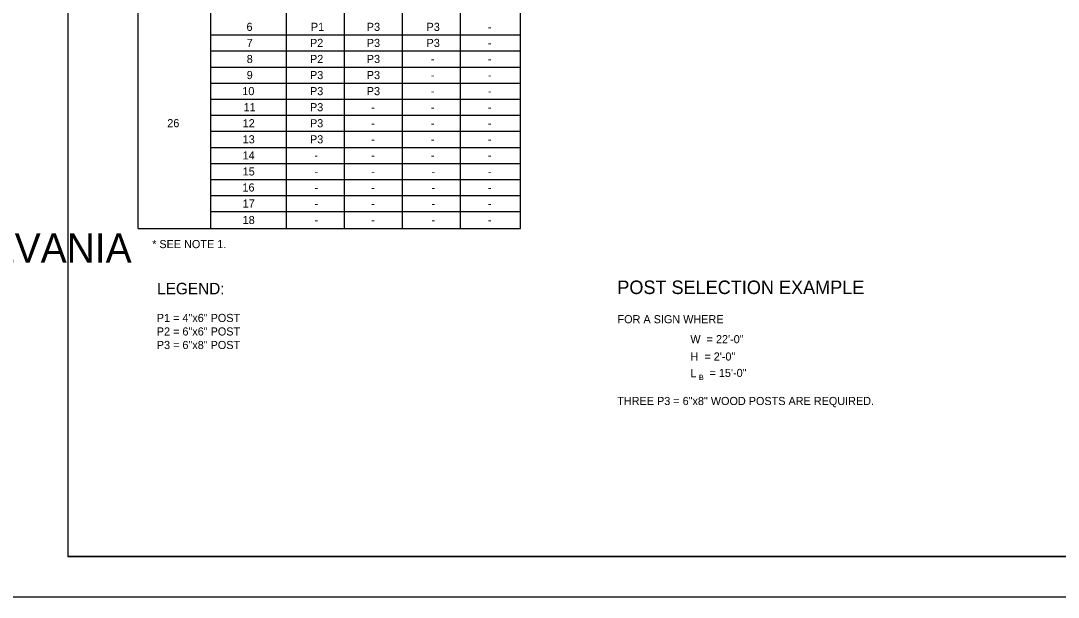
# Model space of a CAD drawing. Extents: x -2340 to 628, y -879 to 309.
# Drawn here: x -253.8 to 130.1, y -284.6 to -71.4 of the extents above; entities that cross this region are included whole.
import ezdxf

# ---------------------------------------------------------------- set-up
doc = ezdxf.new("R2010")
doc.units = 0
for name, color, linetype in [('Level 1', 7, 'Continuous'), ('Level 2', 7, 'Continuous'), ('Level 3', 7, 'Continuous'), ('Level 4', 7, 'Continuous'), ('PLT-BNDY', 7, 'Continuous')]:
    doc.layers.add(name, color=color, linetype=linetype)

msp = doc.modelspace()

# ---------------------------------------------------------------- linework, layer by layer
at = {"layer": 'Level 1'}
for p, q in [((-236.39, 294.44), (-236.39, -269.56)), ((-210.36, -148.17), (-210.36, 265.3)), ((-68.88, -148.17), (-68.88, 265.3)), ((-183.56, -148.17), (-183.56, 257.63)), ((-155.55, -148.17), (-155.55, 257.63)), ((-134.05, -148.17), (-134.05, 250.28)), ((-112.55, -148.17), (-112.55, 250.28)), ((-91.05, -148.17), (-91.05, 250.28)), ((549.61, -269.56), (-236.39, -269.56)), ((-236.39, -269.56), (349.61, -269.56))]:
    msp.add_line(p, q, dxfattribs=at)
at = {"layer": 'Level 2'}
for p, q in [((-183.56, -76.62), (-68.88, -76.62)), ((-183.56, -82.56), (-68.88, -82.56)), ((-108.57, -82.56), (-72.93, -82.56)), ((-183.56, -88.5), (-68.88, -88.5)), ((-183.56, -94.44), (-68.88, -94.44)), ((-108.57, -94.44), (-72.93, -94.44)), ((-183.56, -100.38), (-68.88, -100.38)), ((-183.56, -106.32), (-68.88, -106.32)), ((-108.57, -106.32), (-72.93, -106.32)), ((-183.56, -112.26), (-68.88, -112.26)), ((-183.56, -118.2), (-68.88, -118.2)), ((-183.56, -124.14), (-68.88, -124.14)), ((-183.56, -130.08), (-68.88, -130.08)), ((-183.56, -136.02), (-68.88, -136.02)), ((-183.56, -141.96), (-68.88, -141.96)), ((-210.36, -148.17), (-68.88, -148.17))]:
    msp.add_line(p, q, dxfattribs=at)
at = {"layer": 'PLT-BNDY'}
msp.add_lwpolyline([(-276.39, 309.44), (564.61, 309.44), (564.61, -284.56), (-276.39, -284.56)], close=True, dxfattribs=at)

# ---------------------------------------------------------------- texts
at = {"layer": 'Level 1'}
for s, height, p in [('COMMONWEALTH OF PENNSYLVANIA', 10.7827, (-478.79, -160.83)), ('FOR A SIGN WHERE ', 3, (-33, -183.25)), ('W  = 22\'-0"', 3, (-6.05, -190.63)), ('H  = 2\'-0"', 3, (-5.99, -197.05)), ('L', 3, (-6.04, -203.2)), ('B', 2, (-2.9, -204.26)), (' = 15\'-0"', 3, (-0.06, -203.12)), ('THREE P3 = 6"x8" WOOD POSTS ARE REQUIRED.', 3, (-33.1, -213.49))]:
    msp.add_text(s, height=height, dxfattribs=at).set_placement(p)
at = {"layer": 'Level 2'}
for s, height, p in [('6', 3, (-170.3, -75.14)), ('P1', 3, (-146.47, -75.14)), ('P3', 3, (-125.78, -75.14)), ('P3', 3, (-103.67, -75.14)), ('-', 3, (-80.97, -75.14)), ('7', 3, (-170.22, -81.08)), ('P2', 3, (-146.81, -81.08)), ('P3', 3, (-125.78, -81.08)), ('P3', 3, (-103.67, -81.08)), ('-', 3, (-80.97, -81.08)), ('8', 3, (-170.22, -87.02)), ('P2', 3, (-146.81, -87.02)), ('P3', 3, (-125.78, -87.02)), ('-', 3, (-102.05, -87.02)), ('-', 3, (-80.97, -87.02)), ('9', 3, (-170.23, -92.96)), ('P3', 3, (-146.81, -92.96)), ('P3', 3, (-125.78, -92.96)), ('-', 3, (-102.05, -92.96)), ('-', 3, (-80.97, -92.96)), ('10', 3, (-171.85, -98.9)), ('P3', 3, (-146.81, -98.9)), ('P3', 3, (-125.78, -98.9)), ('-', 3, (-102.05, -98.9)), ('-', 3, (-80.97, -98.9)), ('11', 3, (-171.38, -104.84)), ('P3', 3, (-146.81, -104.84)), ('-', 3, (-124.16, -104.84)), ('-', 3, (-102.05, -104.84)), ('-', 3, (-80.97, -104.84)), ('26', 3, (-199.62, -110.75)), ('12', 3, (-171.72, -110.78)), ('P3', 3, (-146.81, -110.78)), ('-', 3, (-124.16, -110.78)), ('-', 3, (-102.05, -110.78)), ('-', 3, (-80.97, -110.78)), ('13', 3, (-171.72, -116.72)), ('P3', 3, (-146.81, -116.72)), ('-', 3, (-124.16, -116.72)), ('-', 3, (-102.05, -116.72)), ('-', 3, (-80.97, -116.72)), ('14', 3, (-171.72, -122.66)), ('-', 3, (-145.19, -122.66)), ('-', 3, (-124.16, -122.66)), ('-', 3, (-102.05, -122.66)), ('-', 3, (-81.01, -122.66)), ('15', 3, (-171.72, -128.6)), ('-', 3, (-145.15, -128.6)), ('-', 3, (-124.16, -128.6)), ('-', 3, (-101.88, -128.6)), ('-', 3, (-81.01, -128.6)), ('16', 3, (-171.8, -134.54)), ('-', 3, (-145.15, -134.54)), ('-', 3, (-124.16, -134.54)), ('-', 3, (-101.88, -134.54)), ('-', 3, (-81.01, -134.54)), ('17', 3, (-171.72, -140.48)), ('-', 3, (-145.15, -140.48)), ('-', 3, (-124.16, -140.48)), ('-', 3, (-101.88, -140.48)), ('-', 3, (-81.01, -140.48)), ('18', 3, (-171.72, -146.56)), ('-', 3, (-145.15, -146.56)), ('-', 3, (-124.16, -146.56)), ('-', 3, (-101.88, -146.56)), ('-', 3, (-81.01, -146.56)), ('POST SELECTION EXAMPLE', 5, (-33.08, -172.45))]:
    msp.add_text(s, height=height, dxfattribs=at).set_placement(p)
at = {"layer": 'Level 3'}
for s, height, p in [('* SEE NOTE 1.', 3, (-205.22, -155.47)), ('LEGEND:', 4.25, (-203.37, -172.55))]:
    msp.add_text(s, height=height, dxfattribs=at).set_placement(p)
at = {"layer": 'Level 4'}
for s, p in [('P1 = 4"x6" POST', (-203.49, -182.78)), ('P2 = 6"x6" POST', (-203.49, -187.78)), ('P3 = 6"x8" POST', (-203.49, -192.78))]:
    msp.add_text(s, height=3, dxfattribs=at).set_placement(p)

doc.saveas('drawing.dxf')
